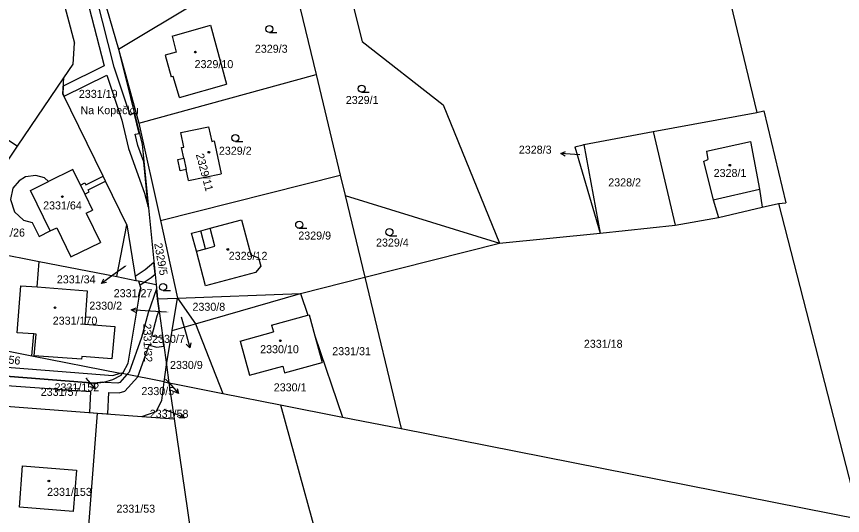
# Model space of a CAD drawing. Extents: x -785744 to -782822, y -1067550 to -1063910.
# Drawn here: x -783790.4 to -783615, y -1066367.5 to -1066261.6 of the extents above; entities that cross this region are included whole.
import ezdxf

# ---------------------------------------------------------------- set-up
doc = ezdxf.new("R2010")
doc.units = 0
for name, color, linetype in [('Hranice parcel', 7, 'Continuous'), ('Parcelní čísla', 7, 'Continuous'), ('Pop_ČP_popisy', 7, 'Continuous'), ('Vnitřní kresba', 7, 'Continuous'), ('Věcná břemena k části', 7, 'Continuous'), ('Značky budov', 7, 'Continuous'), ('Značky kultur', 7, 'Continuous')]:
    doc.layers.add(name, color=color, linetype=linetype)

msp = doc.modelspace()

# ---------------------------------------------------------------- linework, layer by layer
at = {"layer": 'Hranice parcel'}
for p, q in [((-783749.26, -1066306.5), (-783742.57, -1066304.72)), ((-783742.57, -1066304.72), (-783740.61, -1066312.12)), ((-783753.19, -1066307.54), (-783751.26, -1066307.03)), ((-783751.26, -1066307.03), (-783749.26, -1066306.5)), ((-783752.18, -1066311.35), (-783753.19, -1066307.54)), ((-783750.22, -1066318.73), (-783752.18, -1066311.35)), ((-783740.61, -1066312.12), (-783738.98, -1066312.81)), ((-783785.95, -1066318.96), (-783785.53, -1066313.54)), ((-783738.98, -1066312.81), (-783738.51, -1066314.55)), ((-783738.51, -1066314.55), (-783739.66, -1066315.9)), ((-783739.66, -1066315.9), (-783750.22, -1066318.73)), ((-783790.21, -1066328.67), (-783789.45, -1066318.7)), ((-783789.45, -1066318.7), (-783785.95, -1066318.96)), ((-783785.95, -1066318.96), (-783775.35, -1066319.77)), ((-783775.35, -1066319.77), (-783775.89, -1066326.88)), ((-783775.89, -1066326.88), (-783769.48, -1066327.34)), ((-783769.48, -1066327.34), (-783770.16, -1066334.24)), ((-783786.72, -1066328.94), (-783790.21, -1066328.67)), ((-783787.08, -1066333.61), (-783786.72, -1066328.94)), ((-783786.16, -1066328.98), (-783786.72, -1066328.94)), ((-783786.61, -1066333.56), (-783786.16, -1066328.98)), ((-783776.54, -1066334.3), (-783786.61, -1066333.56)), ((-783776.5, -1066333.7), (-783776.54, -1066334.3)), ((-783770.16, -1066334.24), (-783776.5, -1066333.7)), ((-783799.51, -1066337.33), (-783773.77, -1066339.42)), ((-783771.8, -1066339.16), (-783769.9, -1066338.58)), ((-783769.9, -1066338.58), (-783768.17, -1066337.67)), ((-783768.17, -1066337.67), (-783767.94, -1066337.37)), ((-783767.94, -1066337.37), (-783767.72, -1066337.09)), ((-783759, -1066339.13), (-783767.94, -1066337.37)), ((-783773.77, -1066339.42), (-783771.8, -1066339.16)), ((-783795, -1066344.09), (-783773.14, -1066345.75))]:
    msp.add_line(p, q, dxfattribs=at)
for points in [[(-783655.83, -1066187.82), (-783633.19, -1066281.95)], [(-783726.3, -1066229.64), (-783717, -1066266.84)], [(-783783.73, -1066245.88), (-783778.04, -1066267.2)], [(-783733.54, -1066245.75), (-783726.77, -1066273.89)], [(-783771.28, -1066259.71), (-783768.71, -1066268.5)], [(-783768.71, -1066268.5), (-783751.62, -1066258.21)], [(-783757.35, -1066265.73), (-783749.17, -1066263.41)], [(-783749.17, -1066263.41), (-783745.75, -1066275.95)], [(-783757.35, -1066265.73), (-783756.44, -1066269.16)], [(-783778.37, -1066271.68), (-783778.04, -1066267.2)], [(-783768.71, -1066268.5), (-783763.72, -1066288.71)], [(-783768.71, -1066268.5), (-783764.37, -1066284.18)], [(-783717, -1066266.84), (-783699.75, -1066280.34)], [(-783756.44, -1066269.16), (-783758.8, -1066269.79)], [(-783758.8, -1066269.79), (-783757.5, -1066274.38)], [(-783780.33, -1066274.58), (-783778.37, -1066271.68)], [(-783811.62, -1066274.77), (-783790.13, -1066289.08)], [(-783790.13, -1066289.08), (-783780.33, -1066274.58)], [(-783780.54, -1066277.95), (-783780.33, -1066274.58)], [(-783764.37, -1066284.18), (-783726.77, -1066273.89)], [(-783757.1, -1066274.26), (-783757.5, -1066274.38)], [(-783755.78, -1066278.77), (-783757.1, -1066274.26)], [(-783726.77, -1066273.89), (-783721.64, -1066295.21)], [(-783755.78, -1066278.77), (-783745.75, -1066275.95)], [(-783771.96, -1066295.47), (-783780.54, -1066277.95)], [(-783699.75, -1066280.34), (-783687.84, -1066309.64)], [(-783655.22, -1066286), (-783633.19, -1066281.95)], [(-783633.19, -1066281.95), (-783631.68, -1066281.58)], [(-783631.68, -1066281.58), (-783627.03, -1066301.1)], [(-783764.37, -1066284.18), (-783759.8, -1066304.87)], [(-783755.49, -1066286.18), (-783749.58, -1066284.95)], [(-783749.58, -1066284.95), (-783748.93, -1066288.06)], [(-783669.89, -1066288.76), (-783655.22, -1066286)], [(-783655.22, -1066286), (-783650.53, -1066305.87)], [(-783754.84, -1066289.28), (-783755.49, -1066286.18)], [(-783804.17, -1066309.87), (-783790.13, -1066289.08)], [(-783763.72, -1066288.71), (-783760.74, -1066318.41)], [(-783755.35, -1066289.38), (-783754.84, -1066289.28)], [(-783754.87, -1066291.64), (-783755.35, -1066289.38)], [(-783748.93, -1066288.06), (-783748.38, -1066287.94)], [(-783748.38, -1066287.94), (-783746.93, -1066294.92)], [(-783671.84, -1066289.22), (-783670.03, -1066288.79)], [(-783671.84, -1066289.22), (-783666.46, -1066307.57)], [(-783670.03, -1066288.79), (-783669.89, -1066288.76)], [(-783669.89, -1066288.76), (-783666.46, -1066307.57)], [(-783756.11, -1066291.89), (-783754.87, -1066291.64)], [(-783755.6, -1066294.32), (-783756.11, -1066291.89)], [(-783778.43, -1066294.06), (-783783.54, -1066296.57)], [(-783776.81, -1066297.36), (-783778.43, -1066294.06)], [(-783754.36, -1066294.06), (-783755.6, -1066294.32)], [(-783753.88, -1066296.34), (-783754.36, -1066294.06)], [(-783784.39, -1066295.77), (-783786.26, -1066295.28), (-783788.45, -1066295.56), (-783789.83, -1066296.45), (-783791.12, -1066298.01), (-783791.62, -1066300.37), (-783790.79, -1066303.05), (-783788.86, -1066304.77), (-783787.01, -1066305.27), (-783785.54, -1066308.28), (-783783.19, -1066307.06)], [(-783783.54, -1066296.57), (-783784.39, -1066295.77)], [(-783776.81, -1066297.36), (-783775.86, -1066296.85), (-783775.67, -1066297.28), (-783771.96, -1066295.47)], [(-783775.87, -1066299.27), (-783774.94, -1066298.77), (-783775.14, -1066298.36), (-783771.44, -1066296.54)], [(-783771.44, -1066296.54), (-783771.96, -1066295.47)], [(-783766.93, -1066305.75), (-783771.44, -1066296.54)], [(-783759.8, -1066304.87), (-783721.64, -1066295.21)], [(-783753.88, -1066296.34), (-783746.93, -1066294.92)], [(-783721.64, -1066295.21), (-783720.6, -1066299.54)], [(-783775.87, -1066299.27), (-783774.2, -1066302.67)], [(-783720.6, -1066299.54), (-783716.43, -1066316.89)], [(-783720.6, -1066299.54), (-783687.84, -1066309.64)], [(-783632.04, -1066302.03), (-783628.57, -1066301.22)], [(-783628.57, -1066301.22), (-783627.03, -1066301.1)], [(-783628.57, -1066301.22), (-783611.64, -1066367.05)], [(-783775.56, -1066303.33), (-783774.2, -1066302.67)], [(-783775.56, -1066303.33), (-783772.54, -1066309.51)], [(-783641.36, -1066304.21), (-783632.04, -1066302.03)], [(-783759.8, -1066304.87), (-783756.18, -1066321.32)], [(-783650.53, -1066305.87), (-783641.36, -1066304.21)], [(-783783.19, -1066307.06), (-783781.84, -1066306.4)], [(-783781.84, -1066306.4), (-783778.8, -1066312.58)], [(-783769.1, -1066316.77), (-783766.93, -1066305.75)], [(-783766.93, -1066305.75), (-783765.06, -1066317.56)], [(-783666.46, -1066307.57), (-783650.53, -1066305.87)], [(-783687.84, -1066309.64), (-783666.46, -1066307.57)], [(-783804.17, -1066309.87), (-783785.53, -1066313.54)], [(-783778.8, -1066312.58), (-783772.54, -1066309.51)], [(-783716.43, -1066316.89), (-783687.84, -1066309.64)], [(-783785.53, -1066313.54), (-783769.1, -1066316.77)], [(-783769.1, -1066316.77), (-783765.06, -1066317.56)], [(-783765.06, -1066317.56), (-783764.46, -1066317.68)], [(-783730.08, -1066320.35), (-783716.43, -1066316.89)], [(-783716.43, -1066316.89), (-783708.69, -1066349.04)], [(-783764.46, -1066317.68), (-783760.74, -1066318.41)], [(-783764.46, -1066317.68), (-783763.99, -1066319.33)], [(-783764.22, -1066320.71), (-783763.99, -1066319.33)], [(-783760.74, -1066318.41), (-783760.43, -1066321.48)], [(-783766.64, -1066335.17), (-783764.22, -1066320.71)], [(-783756.18, -1066321.32), (-783730.08, -1066320.35)], [(-783752.37, -1066326.78), (-783730.08, -1066320.35)], [(-783730.08, -1066320.35), (-783728.51, -1066324.97)], [(-783760.43, -1066321.48), (-783756.18, -1066321.32)], [(-783760.43, -1066321.48), (-783758.52, -1066335.52)], [(-783757.32, -1066328.21), (-783756.18, -1066321.32)], [(-783756.18, -1066321.32), (-783752.37, -1066326.78)], [(-783736.22, -1066327.07), (-783728.51, -1066324.97)], [(-783728.51, -1066324.97), (-783728.24, -1066324.9)], [(-783728.24, -1066324.9), (-783727.01, -1066329.37)], [(-783757.32, -1066328.21), (-783752.37, -1066326.78)], [(-783752.37, -1066326.78), (-783746.56, -1066341.58)], [(-783736.22, -1066327.07), (-783735.84, -1066328.52)], [(-783758.52, -1066335.52), (-783757.32, -1066328.21)], [(-783742.87, -1066330.47), (-783735.84, -1066328.52)], [(-783727.01, -1066329.37), (-783725.46, -1066335.03)], [(-783727.01, -1066329.37), (-783721.16, -1066346.58)], [(-783800.02, -1066331.07), (-783787.08, -1066333.61)], [(-783742.87, -1066330.47), (-783740.89, -1066337.69)], [(-783787.08, -1066333.61), (-783768.35, -1066337.29)], [(-783767.72, -1066337.09), (-783766.64, -1066335.17)], [(-783733.45, -1066337.2), (-783725.46, -1066335.03)], [(-783799.66, -1066335.46), (-783769.9, -1066337.78)], [(-783759, -1066339.13), (-783758.52, -1066335.52)], [(-783758.52, -1066335.52), (-783758, -1066339.33)], [(-783740.89, -1066337.69), (-783733.84, -1066335.76)], [(-783733.84, -1066335.76), (-783733.45, -1066337.2)], [(-783769.9, -1066337.78), (-783768.35, -1066337.29)], [(-783768.35, -1066337.29), (-783767.72, -1066337.09)], [(-783759.52, -1066343.1), (-783759, -1066339.13)], [(-783759, -1066339.13), (-783758, -1066339.33)], [(-783758, -1066339.33), (-783756.84, -1066339.56)], [(-783758, -1066339.33), (-783756.89, -1066346.98)], [(-783756.84, -1066339.56), (-783746.56, -1066341.58)], [(-783746.56, -1066341.58), (-783734.31, -1066343.99)], [(-783760.74, -1066345.41), (-783759.52, -1066343.1)], [(-783763.73, -1066346.46), (-783760.74, -1066345.41)], [(-783734.31, -1066343.99), (-783702.25, -1066460.74)], [(-783734.31, -1066343.99), (-783721.16, -1066346.58)], [(-783776.14, -1066384.42), (-783773.14, -1066345.75)], [(-783773.14, -1066345.75), (-783763.73, -1066346.46)], [(-783763.73, -1066346.46), (-783756.89, -1066346.98)], [(-783756.89, -1066346.98), (-783751.18, -1066386.35)], [(-783721.16, -1066346.58), (-783708.69, -1066349.04)], [(-783708.69, -1066349.04), (-783611.32, -1066368.29)], [(-783789.09, -1066356.92), (-783777.64, -1066357.85), (-783778.31, -1066366.64), (-783789.76, -1066365.71), (-783789.09, -1066356.92)]]:
    msp.add_lwpolyline(points, dxfattribs=at)
at = {"layer": 'Pop_ČP_popisy'}
for p, q in [((-783671.83, -1066290.83), (-783674.83, -1066290.67)), ((-783769.9, -1066316.45), (-783772.34, -1066318.2)), ((-783763.03, -1066324.01), (-783766.02, -1066323.79)), ((-783754.38, -1066329.02), (-783753.6, -1066331.92)), ((-783775.64, -1066338.31), (-783773.66, -1066340.56)), ((-783757.97, -1066339.35), (-783755.96, -1066341.57)), ((-783757.42, -1066345.57), (-783754.65, -1066346.73))]:
    msp.add_line(p, q, dxfattribs=at)
for points in [[(-783673.85, -1066291.22), (-783674.83, -1066290.67), (-783673.8, -1066290.22)], [(-783670.78, -1066290.89), (-783671.83, -1066290.83)], [(-783767.22, -1066314.52), (-783769.9, -1066316.45)], [(-783771.23, -1066318.02), (-783772.34, -1066318.2), (-783771.82, -1066317.21)], [(-783765.06, -1066324.36), (-783766.02, -1066323.79), (-783764.99, -1066323.37)], [(-783758.53, -1066324.33), (-783763.03, -1066324.01)], [(-783755.39, -1066325.28), (-783754.38, -1066329.02)], [(-783753.38, -1066330.82), (-783753.6, -1066331.92), (-783754.34, -1066331.08)], [(-783758.71, -1066338.53), (-783757.97, -1066339.35)], [(-783773.94, -1066339.48), (-783773.66, -1066340.56), (-783774.69, -1066340.14)], [(-783756.26, -1066340.5), (-783755.96, -1066341.57), (-783757, -1066341.17)], [(-783759.07, -1066344.88), (-783757.42, -1066345.57)], [(-783755.38, -1066345.88), (-783754.65, -1066346.73), (-783755.77, -1066346.8)]]:
    msp.add_lwpolyline(points, dxfattribs=at)
at = {"layer": 'Vnitřní kresba'}
for p, q in [((-783750.24, -1066310.84), (-783751.26, -1066307.03)), ((-783748.26, -1066310.31), (-783749.26, -1066306.5)), ((-783750.24, -1066310.84), (-783748.26, -1066310.31)), ((-783752.18, -1066311.35), (-783750.24, -1066310.84))]:
    msp.add_line(p, q, dxfattribs=at)
for points in [[(-783643.88, -1066290.11), (-783634.55, -1066288.09)], [(-783634.55, -1066288.09), (-783632.61, -1066298.22)], [(-783643.88, -1066290.11), (-783643.58, -1066291.94)], [(-783754.87, -1066291.64), (-783754.36, -1066294.06)], [(-783644.51, -1066292.33), (-783643.58, -1066291.94)], [(-783644.51, -1066292.33), (-783642.47, -1066300.44)], [(-783787.41, -1066298.48), (-783783.54, -1066296.57)], [(-783776.81, -1066297.36), (-783775.87, -1066299.27)], [(-783642.47, -1066300.44), (-783632.61, -1066298.22)], [(-783632.61, -1066298.22), (-783632.04, -1066302.03)], [(-783783.19, -1066307.06), (-783787.41, -1066298.48)], [(-783642.47, -1066300.44), (-783641.36, -1066304.21)]]:
    msp.add_lwpolyline(points, dxfattribs=at)
at = {"layer": 'Věcná břemena k části'}
for p, q in [((-783769.6, -1066272.29), (-783775.08, -1066250.74)), ((-783777.06, -1066251.32), (-783771.78, -1066272.03)), ((-783771.78, -1066272.03), (-783780.44, -1066276.32)), ((-783766.21, -1066282.47), (-783769.6, -1066272.29)), ((-783780.28, -1066278.48), (-783771.2, -1066274.01)), ((-783771.2, -1066274.01), (-783768.02, -1066283.55)), ((-783780.44, -1066276.32), (-783780.54, -1066277.95)), ((-783780.54, -1066277.95), (-783780.28, -1066278.48)), ((-783768.02, -1066283.55), (-783766.57, -1066289.57)), ((-783764.59, -1066288.97), (-783765.18, -1066286.53)), ((-783763.02, -1066315.35), (-783765.18, -1066316.78)), ((-783765.18, -1066316.78), (-783765.06, -1066317.56)), ((-783765.06, -1066317.56), (-783764.46, -1066317.68)), ((-783764.46, -1066317.68), (-783764.21, -1066318.57)), ((-783762.43, -1066324.48), (-783763.84, -1066329.72)), ((-783761.63, -1066329.38), (-783760.47, -1066325.08)), ((-783763.84, -1066329.72), (-783766.46, -1066337.06)), ((-783760.31, -1066329.73), (-783761.63, -1066329.38)), ((-783764.62, -1066338.02), (-783762.22, -1066331.33)), ((-783762.22, -1066331.33), (-783760.55, -1066331.77)), ((-783773.77, -1066339.42), (-783799.51, -1066337.33)), ((-783767.37, -1066341.06), (-783764.62, -1066338.02)), ((-783768.88, -1066339.38), (-783771.64, -1066339.23)), ((-783768.45, -1066339.24), (-783768.88, -1066339.38)), ((-783774.63, -1066341.13), (-783774.85, -1066345.62)), ((-783770.96, -1066345.91), (-783770.73, -1066341.35)), ((-783770.73, -1066341.35), (-783768.56, -1066341.44)), ((-783768.56, -1066341.44), (-783767.37, -1066341.06)), ((-783774.85, -1066345.62), (-783773.14, -1066345.75)), ((-783773.14, -1066345.75), (-783770.96, -1066345.91))]:
    msp.add_line(p, q, dxfattribs=at)
for points in [[(-783764.29, -1066286.41), (-783765.37, -1066282.02), (-783766.21, -1066282.47)], [(-783765.18, -1066286.53), (-783764.29, -1066286.41)], [(-783766.57, -1066289.57), (-783763.16, -1066299.05), (-783762.39, -1066301.97)], [(-783762.39, -1066301.97), (-783763.35, -1066292.44), (-783764.59, -1066288.97)], [(-783760.96, -1066316.25), (-783761.21, -1066313.77), (-783763.02, -1066315.35)], [(-783764.21, -1066318.57), (-783763.23, -1066317.92), (-783761.78, -1066316.97)], [(-783761.78, -1066316.97), (-783760.96, -1066316.25)], [(-783760.09, -1066323.99), (-783760.43, -1066321.48), (-783760.64, -1066319.37), (-783762.43, -1066324.48)], [(-783760.47, -1066325.08), (-783760.09, -1066323.99)], [(-783759.06, -1066331.54), (-783759.33, -1066329.59), (-783760.31, -1066329.73)], [(-783760.55, -1066331.77), (-783759.06, -1066331.54)], [(-783799.51, -1066337.33), (-783799.34, -1066339.41), (-783774.63, -1066341.13)], [(-783766.46, -1066337.06), (-783766.93, -1066337.57), (-783768.45, -1066339.24)], [(-783771.64, -1066339.23), (-783772.15, -1066339.21), (-783773.77, -1066339.42)]]:
    msp.add_lwpolyline(points, dxfattribs=at)
at = {"layer": 'Značky budov'}
for centre in [(-783752.4, -1066269.11), (-783749.52, -1066290.36), (-783638.92, -1066293.12), (-783780.63, -1066299.79), (-783745.51, -1066311.01), (-783782.19, -1066323.37), (-783734.36, -1066330.39), (-783783.49, -1066360.14)]:
    msp.add_circle(centre, 0.175, dxfattribs=at)
at = {"layer": 'Značky kultur'}
for p, q in [((-783736.68, -1066264.96), (-783735.08, -1066264.96)), ((-783717.1, -1066277.63), (-783715.5, -1066277.63)), ((-783743.9, -1066288.09), (-783742.3, -1066288.09)), ((-783730.34, -1066306.52), (-783728.74, -1066306.52)), ((-783711.19, -1066308.08), (-783709.59, -1066308.08)), ((-783759.24, -1066319.74), (-783757.64, -1066319.74))]:
    msp.add_line(p, q, dxfattribs=at)
for centre in [(-783736.68, -1066264.21), (-783717.1, -1066276.88), (-783743.9, -1066287.34), (-783730.34, -1066305.77), (-783711.19, -1066307.33), (-783759.24, -1066318.99)]:
    msp.add_circle(centre, 0.75, dxfattribs=at)

# ---------------------------------------------------------------- texts
at = {"layer": 'Parcelní čísla'}
for s, height, p in [('2329/3', 1.7, (-783739.76, -1066269.25)), ('2329/10', 1.7, (-783752.56, -1066272.51)), ('2331/19', 1.7, (-783777.13, -1066278.83)), ('2329/1', 1.7, (-783720.46, -1066280.13)), ('2329/2', 1.7, (-783747.4, -1066290.9)), ('2328/3', 0.1, (-783670.78, -1066290.89)), ('2328/1', 1.7, (-783642.36, -1066295.62)), ('2328/2', 1.7, (-783664.73, -1066297.62)), ('2331/64', 1.7, (-783784.72, -1066302.51)), ('2331/26', 1.7, (-783796.79, -1066308.27)), ('2329/9', 1.7, (-783730.54, -1066308.91)), ('2329/4', 1.7, (-783714.04, -1066310.39)), ('2329/12', 1.7, (-783745.31, -1066313.2)), ('2331/34', 0.1, (-783767.22, -1066314.52)), ('2331/27', 1.7, (-783769.73, -1066321.14)), ('2330/8', 1.7, (-783753.01, -1066324.02)), ('2330/2', 0.1, (-783758.53, -1066324.33)), ('2331/170', 1.7, (-783782.68, -1066326.97)), ('2330/7', 0.1, (-783755.39, -1066325.28)), ('2330/10', 1.7, (-783738.64, -1066333.03)), ('2331/31', 1.7, (-783723.33, -1066333.45)), ('2331/18', 1.7, (-783669.91, -1066331.88)), ('2330/9', 1.7, (-783757.78, -1066336.37)), ('2331/152', 0.1, (-783775.64, -1066338.31)), ('2330/5', 0.1, (-783758.71, -1066338.53)), ('2331/57', 1.7, (-783785.22, -1066342.08)), ('2330/1', 1.7, (-783735.75, -1066341.13)), ('2331/58', 0.1, (-783759.07, -1066344.88)), ('2331/153', 1.7, (-783783.87, -1066363.31)), ('2331/53', 1.7, (-783769.15, -1066366.88))]:
    msp.add_text(s, height=height, dxfattribs=at).set_placement(p)
for s, rotation, p in [('2329/11', 284.922, (-783752.3, -1066290.87)), ('2329/5', 280.15, (-783761.14, -1066309.78)), ('2331/32', 271.6744, (-783763.47, -1066326.76)), ('2331/56', 353.7622, (-783797.8, -1066334.6))]:
    msp.add_text(s, height=1.7, rotation=rotation, dxfattribs=at).set_placement(p)
at = {"layer": 'Pop_ČP_popisy'}
for s, p in [('Na Kopečku', (-783776.79, -1066282.29)), ('2328/3', (-783683.72, -1066290.67)), ('2331/34', (-783781.81, -1066318.2)), ('2330/2', (-783774.91, -1066323.79)), ('2330/7', (-783761.58, -1066330.83)), ('2331/152', (-783782.29, -1066341.12)), ('2330/5', (-783763.85, -1066341.92)), ('2331/58', (-783762.08, -1066346.73))]:
    msp.add_text(s, height=1.7, dxfattribs=at).set_placement(p)

doc.saveas('drawing.dxf')
